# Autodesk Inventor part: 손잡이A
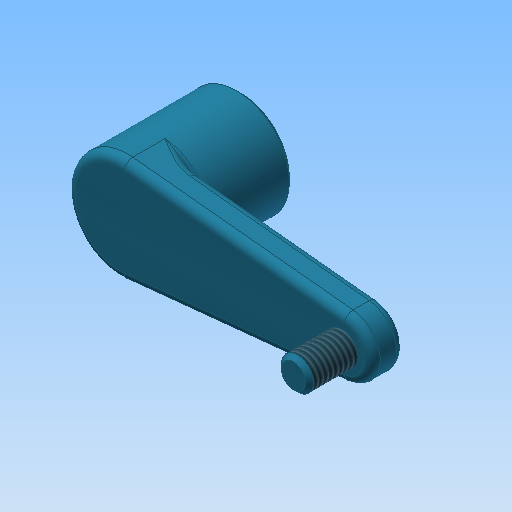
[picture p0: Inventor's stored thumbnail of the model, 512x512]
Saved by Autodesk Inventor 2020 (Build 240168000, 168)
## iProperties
Created: 2022-02
Part Number: 손잡이A
Material: 알루미늄 6061
Document SubType Name: Modeling
Designer: mdu-edu
Density: 2.71 g/cm^3
Mass: 54.7088 g
Surface Area: 71.6588 cm^2
Volume: 20.1877 cm^3
Appearance: 터키옥색
Author: mdu-edu
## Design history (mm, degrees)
sketch "스케치1"
  geometry: C1 r 13 at (0, 0); 1 further point
  constraints: 1 centre point, 1 coincident
  dimensions: "d5" = 13 radius of C1
extrude "돌출1" new body sketch "스케치1" distance "d1" = 22; taper "d2" = 0 deg
sketch "스케치3"
  geometry: L1 (1.3, 12.935)-(55.75, 7.462); L2 (1.3, -12.935)-(55.75, -7.462); C1 r 13 at (0, 0) reference; A1 r 7.5 centre (55, 0) between (55.75, -7.462) and (55.75, 7.462); A2 r 13 centre (0, 0) between (1.3, 12.935) and (1.3, -12.935); 1 further point
  constraints: 4 end point, 4 point on circle, 4 tangent, 2 centre point, 1 coincident, 1 concentric, 1 horizontal alignment
  dimensions: "d15" = 15 diameter of A1; "d16" = 55 distance of point (0, 0) A1.centre
extrude "돌출3" join sketch "스케치3" distance "d17" = 8; taper "d18" = 0 deg
sketch "스케치2"
  geometry: L1 (-7, -7)-(-4.822, -7); L2 (7, -7)-(7, -4.822); L3 (7, 7)-(4.822, 7); L4 (-7, 7)-(-7, 4.822); L5 (-7, -7)-(7, 7); L6 (7, -7)-(-7, 7); L7 (7, 4.822)-(7, 7); L8 (4.822, 7)-(-4.822, 7); L9 (-4.822, 7)-(-7, 7); L10 (-7, 4.822)-(-7, -4.822); L11 (-7, -4.822)-(-7, -7); L12 (-4.822, -7)-(4.822, -7); L13 (4.822, -7)-(7, -7); L14 (7, -4.822)-(7, 4.822); A1 r 8.5 centre (0, 0) between (-4.822, 7) and (-7, 4.822); A2 r 8.5 centre (0, 0) between (4.822, 7) and (-4.822, 7); A3 r 8.5 centre (0, 0) between (7, 4.822) and (4.822, 7); A4 r 8.5 centre (0, 0) between (7, -4.822) and (7, 4.822); A5 r 8.5 centre (0, 0) between (4.822, -7) and (7, -4.822); A6 r 8.5 centre (0, 0) between (-4.822, -7) and (4.822, -7); A7 r 8.5 centre (0, 0) between (-7, -4.822) and (-4.822, -7); A8 r 8.5 centre (0, 0) between (-7, 4.822) and (-7, -4.822); 1 further point
  constraints: 31 point on circle, 28 end point, 18 parallel, 10 perpendicular, 8 centre point, 3 horizontal, 2 midpoint, 1 coincident
  dimensions: "d7" = 14 distance of L2.start L3.start; "d8" = 8.5 radius of A3
extrude "돌출2" cut sketch "스케치2" distance "d9" = 22; taper "d10" = 0 deg
fillet "모깎기1" dims "d30" = 2
fillet "모깎기2" dims "d31" = 2
sketch "스케치4"
  geometry: C1 r 4 at (55, 0); A1 r 7.5 centre (55, 0) between (55.75, -7.462) and (55.75, 7.462) reference; 1 further point
  constraints: 1 centre point, 1 coincident
  dimensions: "d34" = 8 diameter of C1
extrude "돌출4" join sketch "스케치4" distance "d35" = 12; taper "d36" = 0 deg
feature "스레드1" dims "d37" = 10, "d38" = 0
chamfer "모따기1" distance "d12" = 1; stored, may be unused: second distance "d13" = 2, angle "d14" = 45 deg
node "솔리드1"
